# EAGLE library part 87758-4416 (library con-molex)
44 Pin - 2mm Dual Row Single Wafer, Vertical T/H HDR Source: http://www.molex.com/pdm_docs/sd/877580616_sd.pdf
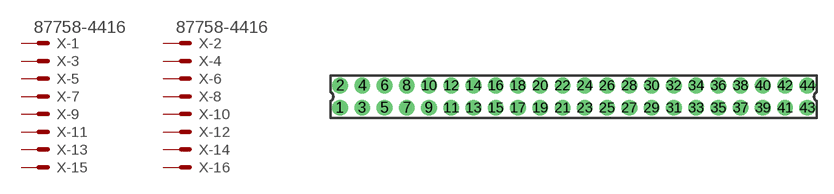
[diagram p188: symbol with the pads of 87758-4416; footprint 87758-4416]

Designator prefix X; gates -1=MV -2=MV -3=M -4=M -5=M -6=M -7=M -8=M -9=M -10=M -11=M -12=M -13=M -14=M -15=M -16=M -17=M -18=M -19=M -20=M -21=M -22=M -23=M -24=M -25=M -26=M -27=M -28=M -29=M -30=M -31=M -32=M -33=M -34=M -35=M -36=M -37=M -38=M -39=M -40=M -41=M -42=M -43=M -44=M

## 87758-4416 (MF: MOLEX; MPN: 87758-4416; OC_FARNELL: unknown; OC_NEWARK: 59J1588)  [87758-4416]
1  -1:S  pas
2  -2:S  pas
3  -3:S  pas
4  -4:S  pas
5  -5:S  pas
6  -6:S  pas
7  -7:S  pas
8  -8:S  pas
9  -9:S  pas
10  -10:S  pas
11  -11:S  pas
12  -12:S  pas
13  -13:S  pas
14  -14:S  pas
15  -15:S  pas
16  -16:S  pas
17  -17:S  pas
18  -18:S  pas
19  -19:S  pas
20  -20:S  pas
21  -21:S  pas
22  -22:S  pas
23  -23:S  pas
24  -24:S  pas
25  -25:S  pas
26  -26:S  pas
27  -27:S  pas
28  -28:S  pas
29  -29:S  pas
30  -30:S  pas
31  -31:S  pas
32  -32:S  pas
33  -33:S  pas
34  -34:S  pas
35  -35:S  pas
36  -36:S  pas
37  -37:S  pas
38  -38:S  pas
39  -39:S  pas
40  -40:S  pas
41  -41:S  pas
42  -42:S  pas
43  -43:S  pas
44  -44:S  pas

## Footprint 87758-4416 (pad centres in mm)
44 Pin - 2mm Dual Row Single Wafer, Vertical T/H HDR Source: http://www.molex.com/pdm_docs/sd/877580616_sd.pdf
drill 0.9 pad 1.27 round: 1 -21,-1; 2 -21,1; 3 -19,-1; 4 -19,1; 5 -17,-1; 6 -17,1; 7 -15,-1; 8 -15,1; 9 -13,-1; 10 -13,1; 11 -11,-1; 12 -11,1; 13 -9,-1; 14 -9,1; 15 -7,-1; 16 -7,1; 17 -5,-1; 18 -5,1; 19 -3,-1; 20 -3,1; 21 -1,-1; 22 -1,1; 23 1,-1; 24 1,1; 25 3,-1; 26 3,1; 27 5,-1; 28 5,1; 29 7,-1; 30 7,1; 31 9,-1; 32 9,1; 33 11,-1; 34 11,1; 35 13,-1; 36 13,1; 37 15,-1; 38 15,1; 39 17,-1; 40 17,1; 41 19,-1; 42 19,1; 43 21,-1; 44 21,1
